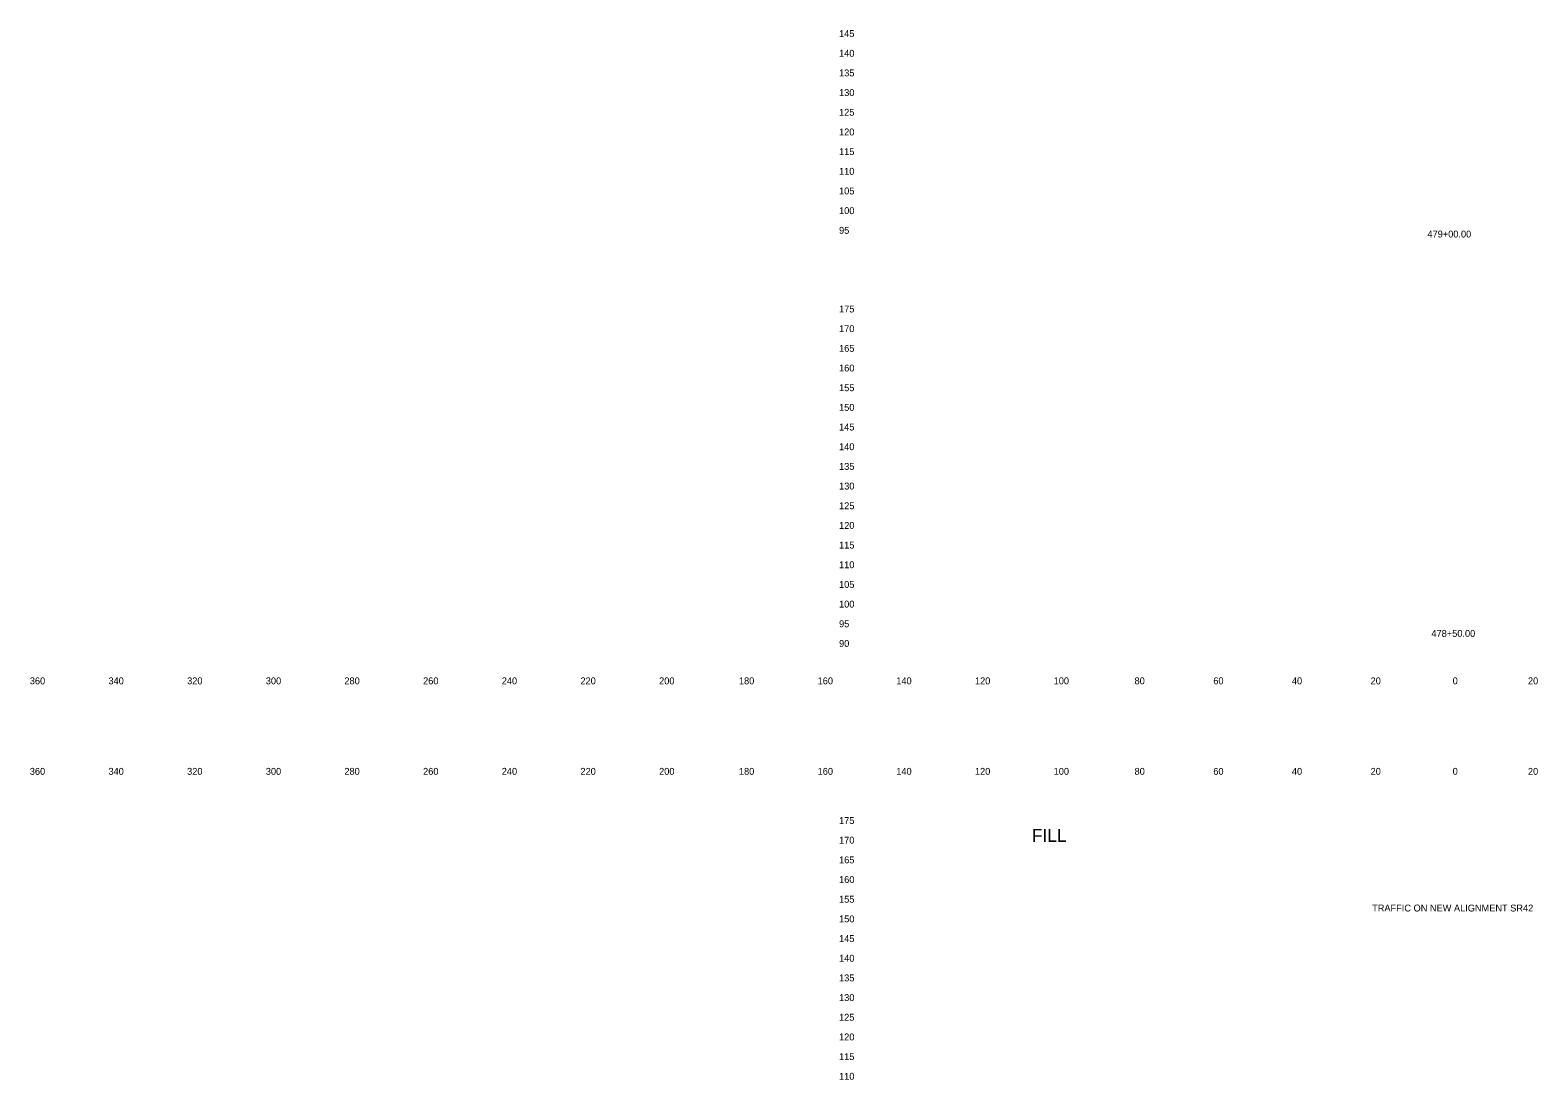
# Model space of a CAD drawing. Extents: x 21281 to 22024, y 6472 to 15208.
# Drawn here: x 21280.5 to 21663.8, y 11664.8 to 11931.6 of the extents above; entities that cross this region are included whole.
import ezdxf

# ---------------------------------------------------------------- set-up
doc = ezdxf.new("R2010")
doc.units = 0
for name, color, linetype in [('XS_SHEET_LABELS_ELEVATION', 7, 'Continuous'), ('XS_SHEET_LABELS_OFFSET', 7, 'Continuous'), ('XS_SHEET_LABELS_STATION', 7, 'Continuous')]:
    doc.layers.add(name, color=color, linetype=linetype)

msp = doc.modelspace()

# ---------------------------------------------------------------- texts
at = {"layer": 'XS_SHEET_LABELS_ELEVATION'}
for s, p in [('  145  ', (21484.84, 11929.84)), ('  140  ', (21484.84, 11924.84)), ('  135  ', (21484.84, 11919.84)), ('  130  ', (21484.84, 11914.84)), ('  125  ', (21484.84, 11909.84)), ('  120  ', (21484.84, 11904.84)), ('  115  ', (21484.84, 11899.84)), ('  110  ', (21484.84, 11894.84)), ('  105  ', (21484.84, 11889.84)), ('  100  ', (21484.84, 11884.84)), ('  95  ', (21484.84, 11879.84)), ('  175  ', (21484.84, 11859.84)), ('  170  ', (21484.84, 11854.84)), ('  165  ', (21484.84, 11849.84)), ('  160  ', (21484.84, 11844.84)), ('  155  ', (21484.84, 11839.84)), ('  150  ', (21484.84, 11834.84)), ('  145  ', (21484.84, 11829.84)), ('  140  ', (21484.84, 11824.84)), ('  135  ', (21484.84, 11819.84)), ('  130  ', (21484.84, 11814.84)), ('  125  ', (21484.84, 11809.84)), ('  120  ', (21484.84, 11804.84)), ('  115  ', (21484.84, 11799.84)), ('  110  ', (21484.84, 11794.84)), ('  105  ', (21484.84, 11789.84)), ('  100  ', (21484.84, 11784.84)), ('  95  ', (21484.84, 11779.84)), ('  90  ', (21484.84, 11774.84)), ('  175  ', (21484.84, 11729.84)), ('  170  ', (21484.84, 11724.84)), ('  165  ', (21484.84, 11719.84)), ('  160  ', (21484.84, 11714.84)), ('  155  ', (21484.84, 11709.84)), ('  150  ', (21484.84, 11704.84)), ('  145  ', (21484.84, 11699.84)), ('  140  ', (21484.84, 11694.84)), ('  135  ', (21484.84, 11689.84)), ('  130  ', (21484.84, 11684.84)), ('  125  ', (21484.84, 11679.84)), ('  120  ', (21484.84, 11674.84)), ('  115  ', (21484.84, 11669.84)), ('  110  ', (21484.84, 11664.84))]:
    msp.add_text(s, height=1.75, dxfattribs=at).set_placement(p)
at = {"layer": 'XS_SHEET_LABELS_OFFSET'}
for s, height, p in [('  360  ', 1.75, (21279.14, 11765.34)), ('  340  ', 1.75, (21299.13, 11765.34)), ('  320  ', 1.75, (21319.13, 11765.34)), ('  300  ', 1.75, (21339.13, 11765.34)), ('  280  ', 1.75, (21359.1, 11765.34)), ('  260  ', 1.75, (21379.11, 11765.34)), ('  240  ', 1.75, (21399.1, 11765.34)), ('  220  ', 1.75, (21419.1, 11765.34)), ('  200  ', 1.75, (21439.1, 11765.34)), ('  180  ', 1.75, (21459.39, 11765.34)), ('  160  ', 1.75, (21479.4, 11765.34)), ('  140  ', 1.75, (21499.39, 11765.34)), ('  120  ', 1.75, (21519.39, 11765.34)), ('  100  ', 1.75, (21539.39, 11765.34)), ('  80  ', 1.75, (21559.95, 11765.34)), ('  60  ', 1.75, (21579.97, 11765.34)), ('  40  ', 1.75, (21599.95, 11765.34)), ('  20  ', 1.75, (21619.95, 11765.34)), ('  0  ', 1.75, (21640.81, 11765.34)), ('  0  ', 1.75, (21640.81, 11765.34)), ('  20  ', 1.75, (21659.95, 11765.34)), ('  360  ', 1.75, (21279.14, 11742.34)), ('  340  ', 1.75, (21299.13, 11742.34)), ('  320  ', 1.75, (21319.13, 11742.34)), ('  300  ', 1.75, (21339.13, 11742.34)), ('  280  ', 1.75, (21359.1, 11742.34)), ('  260  ', 1.75, (21379.11, 11742.34)), ('  240  ', 1.75, (21399.1, 11742.34)), ('  220  ', 1.75, (21419.1, 11742.34)), ('  200  ', 1.75, (21439.1, 11742.34)), ('  180  ', 1.75, (21459.39, 11742.34)), ('  160  ', 1.75, (21479.4, 11742.34)), ('  140  ', 1.75, (21499.39, 11742.34)), ('  120  ', 1.75, (21519.39, 11742.34)), ('  100  ', 1.75, (21539.39, 11742.34)), ('  80  ', 1.75, (21559.95, 11742.34)), ('  60  ', 1.75, (21579.97, 11742.34)), ('  40  ', 1.75, (21599.95, 11742.34)), ('  20  ', 1.75, (21619.95, 11742.34)), ('  0  ', 1.75, (21640.81, 11742.34)), ('  0  ', 1.75, (21640.81, 11742.34)), ('  20  ', 1.75, (21659.95, 11742.34)), ('FILL', 3.273, (21535.18, 11725.29))]:
    msp.add_text(s, height=height, dxfattribs=at).set_placement(p)
at = {"layer": 'XS_SHEET_LABELS_STATION'}
for s, p in [('  479+00.00  ', (21634.4, 11878.89)), ('  478+50.00  ', (21635.42, 11777.39)), ('TRAFFIC ON NEW ALIGNMENT SR42', (21621.64, 11707.6))]:
    msp.add_text(s, height=1.75, dxfattribs=at).set_placement(p)

doc.saveas('drawing.dxf')
